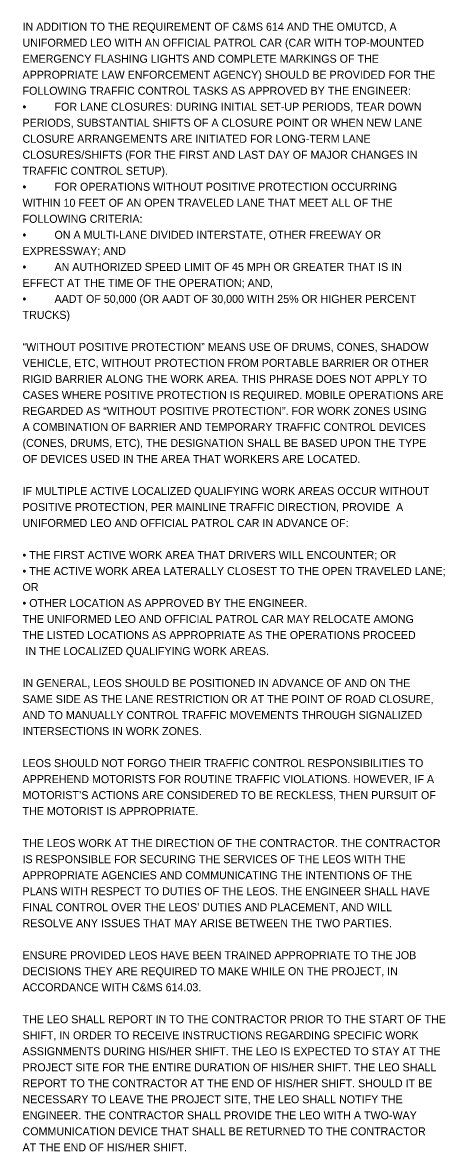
# Model space of a CAD drawing. Extents: x 0 to 53.7, y -25.8 to 22.
# Drawn here: x 30.24 to 37.65, y -25.8 to -6.05 of the extents above; entities that cross this region are included whole.
import ezdxf

# ---------------------------------------------------------------- set-up
doc = ezdxf.new("R2010")
doc.units = 0
doc.layers.add('SH_Text', color=7, linetype='Continuous')

msp = doc.modelspace()

# ---------------------------------------------------------------- texts
at = {"layer": 'SH_Text'}
for s, p in [('IN ADDITION TO THE REQUIREMENT OF C&MS 614 AND THE OMUTCD, A ', (30.243, -6.195)), ('UNIFORMED LEO WITH AN OFFICIAL PATROL CAR (CAR WITH TOP-MOUNTED ', (30.243, -6.475)), ('EMERGENCY FLASHING LIGHTS AND COMPLETE MARKINGS OF THE ', (30.243, -6.755)), ('APPROPRIATE LAW ENFORCEMENT AGENCY) SHOULD BE PROVIDED FOR THE ', (30.243, -7.035)), ('FOLLOWING TRAFFIC CONTROL TASKS AS APPROVED BY THE ENGINEER: ', (30.243, -7.315)), ('•', (30.243, -7.595)), ('FOR LANE CLOSURES: DURING INITIAL SET-UP PERIODS, TEAR DOWN ', (30.803, -7.595)), ('PERIODS, SUBSTANTIAL SHIFTS OF A CLOSURE POINT OR WHEN NEW LANE ', (30.243, -7.875)), ('CLOSURE ARRANGEMENTS ARE INITIATED FOR LONG-TERM LANE ', (30.243, -8.155)), ('CLOSURES/SHIFTS (FOR THE FIRST AND LAST DAY OF MAJOR CHANGES IN ', (30.243, -8.435)), ('TRAFFIC CONTROL SETUP).', (30.243, -8.715)), ('FOR OPERATIONS WITHOUT POSITIVE PROTECTION OCCURRING ', (30.803, -8.995)), ('•', (30.243, -8.995)), ('WITHIN 10 FEET OF AN OPEN TRAVELED LANE THAT MEET ALL OF THE ', (30.243, -9.275)), ('FOLLOWING CRITERIA:', (30.243, -9.555)), ('•', (30.243, -9.835)), ('ON A MULTI-LANE DIVIDED INTERSTATE, OTHER FREEWAY OR ', (30.803, -9.835)), ('EXPRESSWAY; AND', (30.243, -10.115)), ('AN AUTHORIZED SPEED LIMIT OF 45 MPH OR GREATER THAT IS IN ', (30.803, -10.395)), ('•', (30.243, -10.395)), ('EFFECT AT THE TIME OF THE OPERATION; AND,', (30.243, -10.675)), ('AADT OF 50,000 (OR AADT OF 30,000 WITH 25% OR HIGHER PERCENT ', (30.803, -10.955)), ('•', (30.243, -10.955)), ('TRUCKS)', (30.243, -11.235)), ('“WITHOUT POSITIVE PROTECTION” MEANS USE OF DRUMS, CONES, SHADOW ', (30.243, -11.795)), ('VEHICLE, ETC, WITHOUT PROTECTION FROM PORTABLE BARRIER OR OTHER ', (30.243, -12.075)), ('RIGID BARRIER ALONG THE WORK AREA. THIS PHRASE DOES NOT APPLY TO ', (30.243, -12.355)), ('CASES WHERE POSITIVE PROTECTION IS REQUIRED. MOBILE OPERATIONS ARE ', (30.243, -12.635)), ('REGARDED AS “WITHOUT POSITIVE PROTECTION”. FOR WORK ZONES USING ', (30.243, -12.915)), ('A COMBINATION OF BARRIER AND TEMPORARY TRAFFIC CONTROL DEVICES ', (30.243, -13.195)), ('(CONES, DRUMS, ETC), THE DESIGNATION SHALL BE BASED UPON THE TYPE ', (30.243, -13.475)), ('OF DEVICES USED IN THE AREA THAT WORKERS ARE LOCATED.', (30.243, -13.755)), ('IF MULTIPLE ACTIVE LOCALIZED QUALIFYING WORK AREAS OCCUR WITHOUT ', (30.243, -14.315)), ('POSITIVE PROTECTION, PER MAINLINE TRAFFIC DIRECTION, PROVIDE  A ', (30.243, -14.595)), ('UNIFORMED LEO AND OFFICIAL PATROL CAR IN ADVANCE OF:', (30.243, -14.875)), ('• THE FIRST ACTIVE WORK AREA THAT DRIVERS WILL ENCOUNTER; OR', (30.243, -15.435)), ('• THE ACTIVE WORK AREA LATERALLY CLOSEST TO THE OPEN TRAVELED LANE; ', (30.243, -15.715)), ('OR', (30.243, -15.995)), ('• OTHER LOCATION AS APPROVED BY THE ENGINEER.', (30.243, -16.275)), ('THE UNIFORMED LEO AND OFFICIAL PATROL CAR MAY RELOCATE AMONG ', (30.243, -16.555)), ('THE LISTED LOCATIONS AS APPROPRIATE AS THE OPERATIONS PROCEED', (30.243, -16.835)), (' IN THE LOCALIZED QUALIFYING WORK AREAS.', (30.243, -17.115)), ('IN GENERAL, LEOS SHOULD BE POSITIONED IN ADVANCE OF AND ON THE ', (30.243, -17.675)), ('SAME SIDE AS THE LANE RESTRICTION OR AT THE POINT OF ROAD CLOSURE, ', (30.243, -17.955)), ('AND TO MANUALLY CONTROL TRAFFIC MOVEMENTS THROUGH SIGNALIZED ', (30.243, -18.235)), ('INTERSECTIONS IN WORK ZONES. ', (30.243, -18.515)), ('LEOS SHOULD NOT FORGO THEIR TRAFFIC CONTROL RESPONSIBILITIES TO ', (30.243, -19.075)), ('APPREHEND MOTORISTS FOR ROUTINE TRAFFIC VIOLATIONS. HOWEVER, IF A ', (30.243, -19.355)), ('MOTORIST’S ACTIONS ARE CONSIDERED TO BE RECKLESS, THEN PURSUIT OF ', (30.243, -19.635)), ('THE MOTORIST IS APPROPRIATE. ', (30.243, -19.915)), ('THE LEOS WORK AT THE DIRECTION OF THE CONTRACTOR. THE CONTRACTOR ', (30.243, -20.475)), ('IS RESPONSIBLE FOR SECURING THE SERVICES OF THE LEOS WITH THE ', (30.243, -20.755)), ('APPROPRIATE AGENCIES AND COMMUNICATING THE INTENTIONS OF THE ', (30.243, -21.035)), ('PLANS WITH RESPECT TO DUTIES OF THE LEOS. THE ENGINEER SHALL HAVE ', (30.243, -21.315)), ('FINAL CONTROL OVER THE LEOS’ DUTIES AND PLACEMENT, AND WILL ', (30.243, -21.595)), ('RESOLVE ANY ISSUES THAT MAY ARISE BETWEEN THE TWO PARTIES. ', (30.243, -21.875)), ('ENSURE PROVIDED LEOS HAVE BEEN TRAINED APPROPRIATE TO THE JOB ', (30.243, -22.435)), ('DECISIONS THEY ARE REQUIRED TO MAKE WHILE ON THE PROJECT, IN ', (30.243, -22.715)), ('ACCORDANCE WITH C&MS 614.03. ', (30.243, -22.995)), ('THE LEO SHALL REPORT IN TO THE CONTRACTOR PRIOR TO THE START OF THE ', (30.243, -23.555)), ('SHIFT, IN ORDER TO RECEIVE INSTRUCTIONS REGARDING SPECIFIC WORK ', (30.243, -23.835)), ('ASSIGNMENTS DURING HIS/HER SHIFT. THE LEO IS EXPECTED TO STAY AT THE ', (30.243, -24.115)), ('PROJECT SITE FOR THE ENTIRE DURATION OF HIS/HER SHIFT. THE LEO SHALL ', (30.243, -24.395)), ('REPORT TO THE CONTRACTOR AT THE END OF HIS/HER SHIFT. SHOULD IT BE ', (30.243, -24.675)), ('NECESSARY TO LEAVE THE PROJECT SITE, THE LEO SHALL NOTIFY THE ', (30.243, -24.955)), ('ENGINEER. THE CONTRACTOR SHALL PROVIDE THE LEO WITH A TWO-WAY ', (30.243, -25.235)), ('COMMUNICATION DEVICE THAT SHALL BE RETURNED TO THE CONTRACTOR ', (30.243, -25.515)), ('AT THE END OF HIS/HER SHIFT.', (30.243, -25.795))]:
    msp.add_text(s, height=0.14, dxfattribs=at).set_placement(p)

doc.saveas('drawing.dxf')
